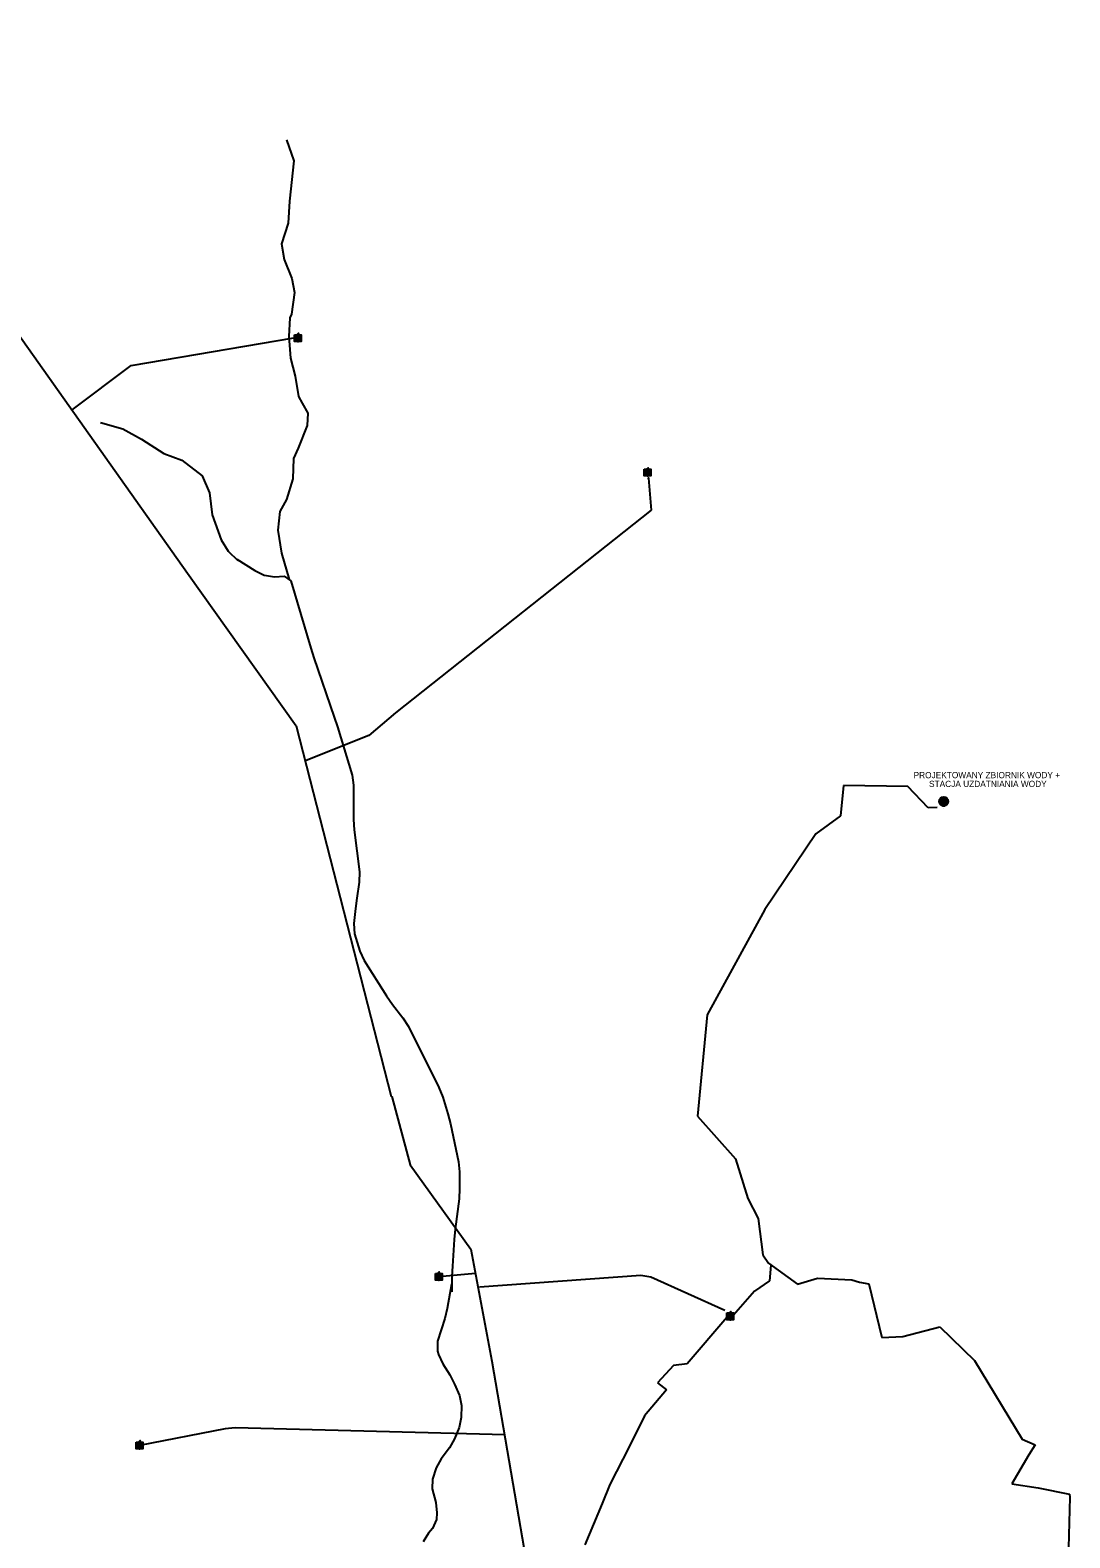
# Model space of a CAD drawing. Extents: x -562329 to -547582, y 191173 to 206137.
# Drawn here: x -557916 to -555907, y 202704 to 205618 of the extents above; entities that cross this region are included whole.
import ezdxf

# ---------------------------------------------------------------- set-up
doc = ezdxf.new("R2010")
doc.units = 0
for name, color, linetype in [('nazwy miejscowości', 7, 'Continuous'), ('nazwy miejscowości DUŻE', 7, 'Continuous'), ('opisy', 7, 'Continuous'), ('ramki A3_A', 7, 'Continuous'), ('strefa - cmentarz', 7, 'Continuous'), ('zmiany', 7, 'Continuous')]:
    doc.layers.add(name, color=color, linetype=linetype)

msp = doc.modelspace()

# ---------------------------------------------------------------- linework, layer by layer
at = {"layer": 'nazwy miejscowości'}
for p, q in [((-556720.8, 204754), (-556723.3, 204751.4)), ((-556721.6, 204752.3), (-556716.5, 204690.4)), ((-556719.9, 204728.5), (-556719.9, 204728.5)), ((-556716.5, 204690.4), (-557210.5, 204299)), ((-557210.5, 204299), (-557262.2, 204254.9)), ((-557262.2, 204254.9), (-557383.3, 204206.6)), ((-557055.8, 203215.2), (-557126.8, 203208.9)), ((-557048.2, 203189.8), (-556736.2, 203212)), ((-556736.2, 203212), (-556717.1, 203208.6)), ((-556717.1, 203208.6), (-556574, 203144.2))]:
    msp.add_line(p, q, dxfattribs=at)
for points in [[(-558670.2, 205618.4), (-558633.4, 205559), (-558588.2, 205493.7), (-557970.8, 205075.8), (-557612.3, 204568.8)], [(-557835.5, 204884.6), (-557721.5, 204970.1), (-557406.9, 205023.5)], [(-557612.3, 204568.8), (-557402.2, 204273.9), (-557219, 203557.1)], [(-557217.5, 203557.5), (-557181.9, 203425), (-557065.2, 203262.5), (-557024.6, 203046), (-556950.7, 202618.3), (-556938.9, 202550.3)]]:
    msp.add_lwpolyline(points, dxfattribs=at)
at = {"layer": 'nazwy miejscowości DUŻE'}
for p, q in [((-557539.8, 202915.3), (-557704.9, 202883)), ((-557520, 202917), (-557539.8, 202915.3)), ((-556998.8, 202903.3), (-557520, 202917))]:
    msp.add_line(p, q, dxfattribs=at)
at = {"layer": 'opisy'}
for p, q in [((-556344.9, 204158.5), (-556350.4, 204099.9)), ((-556344.9, 204158.5), (-556350.4, 204099.9)), ((-556220.4, 204156.7), (-556344.9, 204158.5)), ((-556220.4, 204156.7), (-556344.9, 204158.5)), ((-556180.9, 204115.2), (-556220.4, 204156.7)), ((-556180.9, 204115.2), (-556220.4, 204156.7)), ((-556350.4, 204099.9), (-556398, 204065.1)), ((-556350.4, 204099.9), (-556398, 204065.1)), ((-556163.5, 204115.9), (-556180.9, 204115.2)), ((-556163.5, 204115.9), (-556180.9, 204115.2)), ((-556398, 204065.1), (-556496.9, 203918.7)), ((-556398, 204065.1), (-556496.9, 203918.7)), ((-556496.9, 203918.7), (-556608.5, 203715.5)), ((-556496.9, 203918.7), (-556608.5, 203715.5)), ((-556608.5, 203715.5), (-556626.9, 203519.6)), ((-556608.5, 203715.5), (-556626.9, 203519.6)), ((-556626.9, 203519.6), (-556553.6, 203437.2)), ((-556626.9, 203519.6), (-556553.6, 203437.2)), ((-556553.6, 203437.2), (-556529.8, 203360.3)), ((-556553.6, 203437.2), (-556529.8, 203360.3)), ((-556529.8, 203360.3), (-556509.7, 203321.8)), ((-556529.8, 203360.3), (-556509.7, 203321.8)), ((-556509.7, 203321.8), (-556500.9, 203251.4)), ((-556509.7, 203321.8), (-556500.9, 203251.4)), ((-556500.9, 203251.4), (-556489.6, 203235)), ((-556500.9, 203251.4), (-556489.6, 203235)), ((-556489.6, 203235), (-556433.7, 203194.5)), ((-556489.6, 203235), (-556433.7, 203194.5)), ((-556485.1, 203231.7), (-556487.7, 203201.1)), ((-556487.7, 203201.1), (-556516.7, 203180.9)), ((-556433.7, 203194.5), (-556394.9, 203206.5)), ((-556433.7, 203194.5), (-556394.9, 203206.5)), ((-556394.9, 203206.5), (-556328.6, 203203.1)), ((-556394.9, 203206.5), (-556328.6, 203203.1)), ((-556328.6, 203203.1), (-556314.2, 203198.6)), ((-556328.6, 203203.1), (-556314.2, 203198.6)), ((-556314.2, 203198.6), (-556295.6, 203195.4)), ((-556314.2, 203198.6), (-556295.6, 203195.4)), ((-556295.6, 203195.4), (-556270.6, 203091.3)), ((-556295.6, 203195.4), (-556270.6, 203091.3)), ((-556516.7, 203180.9), (-556557.1, 203134.9)), ((-556570, 203130), (-556646.7, 203040.5)), ((-556557.1, 203134.9), (-556570, 203130)), ((-556230.3, 203093.7), (-556158.4, 203112.3)), ((-556230.3, 203093.7), (-556158.4, 203112.3)), ((-556158.4, 203112.3), (-556091.4, 203046.9)), ((-556158.4, 203112.3), (-556091.4, 203046.9)), ((-556270.6, 203091.3), (-556230.3, 203093.7)), ((-556270.6, 203091.3), (-556230.3, 203093.7)), ((-556673.3, 203037.2), (-556704, 203004.2)), ((-556646.7, 203040.5), (-556673.3, 203037.2)), ((-556091.4, 203046.9), (-555999.4, 202894.8)), ((-556091.4, 203046.9), (-555999.4, 202894.8)), ((-556687, 202990.4), (-556729, 202940.4)), ((-556704, 203004.2), (-556687, 202990.4)), ((-556729, 202940.4), (-556758, 202881.5)), ((-556758, 202881.5), (-556796, 202807.2)), ((-555999.4, 202894.8), (-555974.4, 202883.9)), ((-555974.4, 202883.9), (-555986.5, 202864.5)), ((-555986.5, 202864.5), (-556019.6, 202808.9)), ((-556796, 202807.2), (-556811.3, 202770.9)), ((-556019.6, 202808.9), (-555968.8, 202800.8)), ((-555968.8, 202800.8), (-555908.3, 202788.7)), ((-555908.3, 202788.7), (-555907.5, 202783)), ((-556811.3, 202770.9), (-556844.4, 202690.6)), ((-555907.5, 202783), (-555910.7, 202660.4))]:
    msp.add_line(p, q, dxfattribs=at)
at = {"layer": 'ramki A3_A'}
for p, q in [((-557399.6, 205029.7), (-557402.1, 205021.4)), ((-557401.1, 205029.7), (-557399.6, 205029.7)), ((-557400, 205023.6), (-557398.1, 205029.7)), ((-557398.1, 205029.7), (-557396.6, 205029.7)), ((-557403.6, 205018.4), (-557403.6, 205027.9)), ((-557403.6, 205027.9), (-557400.1, 205027.9)), ((-557399.1, 205018.4), (-557403.6, 205018.4)), ((-557402.1, 205021.4), (-557397.8, 205022.8)), ((-557395.6, 205025), (-557400, 205023.6)), ((-557397.8, 205022.8), (-557399.6, 205016.7)), ((-557399.6, 205016.7), (-557398.1, 205016.7)), ((-557399.6, 205016.7), (-557398.1, 205016.7)), ((-557398.6, 205027.9), (-557394.1, 205027.9)), ((-557398.1, 205016.7), (-557395.6, 205025)), ((-557394.1, 205018.4), (-557397.6, 205018.4)), ((-557394.1, 205027.9), (-557394.1, 205018.4)), ((-556728.1, 204758.4), (-556728.1, 204767.9)), ((-556728.1, 204767.9), (-556724.6, 204767.9)), ((-556724.1, 204769.6), (-556726.6, 204761.3)), ((-556725.6, 204769.6), (-556724.1, 204769.6)), ((-556724.4, 204763.6), (-556722.6, 204769.6)), ((-556723.1, 204767.9), (-556718.6, 204767.9)), ((-556722.6, 204769.6), (-556721.1, 204769.6)), ((-556718.6, 204767.9), (-556718.6, 204758.4)), ((-556723.6, 204758.4), (-556728.1, 204758.4)), ((-556726.6, 204761.3), (-556722.3, 204762.8)), ((-556720.1, 204765), (-556724.4, 204763.6)), ((-556722.3, 204762.8), (-556724.1, 204756.7)), ((-556724.1, 204756.7), (-556722.6, 204756.7)), ((-556724.1, 204756.7), (-556722.6, 204756.7)), ((-556722.6, 204756.7), (-556720.1, 204765)), ((-556718.6, 204758.4), (-556722.1, 204758.4)), ((-557131.6, 203204.1), (-557131.6, 203213.6)), ((-557131.6, 203213.6), (-557128.1, 203213.6)), ((-557127, 203204.1), (-557131.6, 203204.1)), ((-557127.6, 203215.3), (-557130.1, 203207)), ((-557130.1, 203207), (-557125.7, 203208.5)), ((-557129.1, 203215.3), (-557127.6, 203215.3)), ((-557127.9, 203209.2), (-557126.1, 203215.3)), ((-557123.6, 203210.7), (-557127.9, 203209.2)), ((-557125.7, 203208.5), (-557127.6, 203202.4)), ((-557127.6, 203202.4), (-557126.1, 203202.4)), ((-557127.6, 203202.4), (-557126.1, 203202.4)), ((-557126.6, 203213.6), (-557122.1, 203213.6)), ((-557126.1, 203215.3), (-557124.6, 203215.3)), ((-557126.1, 203202.4), (-557123.6, 203210.7)), ((-557122.1, 203204.1), (-557125.6, 203204.1)), ((-557122.1, 203213.6), (-557122.1, 203204.1)), ((-556568.3, 203127.7), (-556568.3, 203137.2)), ((-556568.3, 203137.2), (-556564.8, 203137.2)), ((-556564.3, 203139), (-556566.8, 203130.6)), ((-556565.8, 203139), (-556564.3, 203139)), ((-556564.6, 203132.9), (-556562.8, 203139)), ((-556563.3, 203137.2), (-556558.8, 203137.2)), ((-556562.8, 203139), (-556561.3, 203139)), ((-556558.8, 203137.2), (-556558.8, 203127.7)), ((-556563.8, 203127.7), (-556568.3, 203127.7)), ((-556566.8, 203130.6), (-556562.5, 203132.1)), ((-556560.3, 203134.3), (-556564.6, 203132.9)), ((-556562.5, 203132.1), (-556564.3, 203126)), ((-556564.3, 203126), (-556562.8, 203126)), ((-556564.3, 203126), (-556562.8, 203126)), ((-556562.8, 203126), (-556560.3, 203134.3)), ((-556558.8, 203127.7), (-556562.3, 203127.7)), ((-557709.7, 202878.3), (-557709.7, 202887.8)), ((-557709.7, 202887.8), (-557706.2, 202887.8)), ((-557705.2, 202878.3), (-557709.7, 202878.3)), ((-557705.7, 202889.5), (-557708.2, 202881.2)), ((-557708.2, 202881.2), (-557703.9, 202882.6)), ((-557707.2, 202889.5), (-557705.7, 202889.5)), ((-557706, 202883.4), (-557704.2, 202889.5)), ((-557701.7, 202884.9), (-557706, 202883.4)), ((-557703.9, 202882.6), (-557705.7, 202876.5)), ((-557705.7, 202876.5), (-557704.2, 202876.5)), ((-557705.7, 202876.5), (-557704.2, 202876.5)), ((-557704.7, 202887.8), (-557700.2, 202887.8)), ((-557704.2, 202889.5), (-557702.7, 202889.5)), ((-557704.2, 202876.5), (-557701.7, 202884.9)), ((-557700.2, 202878.3), (-557703.7, 202878.3)), ((-557700.2, 202887.8), (-557700.2, 202878.3))]:
    msp.add_line(p, q, dxfattribs=at)
for points in [[(-557405.4, 205029.7), (-557392.4, 205029.7), (-557392.4, 205016.7), (-557405.4, 205016.7)], [(-556729.8, 204769.6), (-556716.9, 204769.6), (-556716.9, 204756.7), (-556729.8, 204756.7)], [(-557133.3, 203215.3), (-557120.3, 203215.3), (-557120.3, 203202.4), (-557133.3, 203202.4)], [(-556570, 203139), (-556557.1, 203139), (-556557.1, 203126), (-556570, 203126)], [(-557711.4, 202889.5), (-557698.5, 202889.5), (-557698.5, 202876.5), (-557711.4, 202876.5)]]:
    msp.add_lwpolyline(points, close=True, dxfattribs=at)
for points in [[(-557396.6, 205029.7), (-557398, 205032.5), (-557401.1, 205029.7)], [(-556721.1, 204769.6), (-556722.5, 204772.5), (-556725.6, 204769.6)], [(-557124.6, 203215.3), (-557126, 203218.2), (-557129.1, 203215.3)], [(-556561.3, 203139), (-556562.7, 203141.8), (-556565.8, 203139)], [(-557702.7, 202889.5), (-557704.1, 202892.4), (-557707.2, 202889.5)]]:
    msp.add_lwpolyline(points, dxfattribs=at)
at = {"layer": 'strefa - cmentarz'}
for p, q in [((-556157.2, 204127.8), (-556159.8, 204127.8)), ((-556147.7, 204127.8), (-556154.6, 204127.8)), ((-556142.5, 204127.8), (-556145.1, 204127.8)), ((-556151.2, 204114.3), (-556151.2, 204114.3))]:
    msp.add_line(p, q, dxfattribs=at)
for radius in [8.66, 6.06, 3.46]:
    msp.add_circle((-556151.2, 204127.8), radius, dxfattribs=at)
for radius, start, end in [(8.66, 180, 240), (6.06, 180, 0), (8.66, 240, 0), (3.46, 180, 240), (3.46, 240, 0)]:
    msp.add_arc((-556151.2, 204127.8), radius, start, end, dxfattribs=at)
at = {"layer": 'zmiany'}
for p, q in [((-557517, 204595.8), (-557482.3, 204574)), ((-557482.3, 204574), (-557464.4, 204565.1)), ((-557464.4, 204565.1), (-557463.4, 204564.7)), ((-557463.4, 204564.7), (-557444.1, 204561.9)), ((-557444.1, 204561.9), (-557425.8, 204563.1)), ((-557425.8, 204563.1), (-557413, 204554.1)), ((-557413, 204554.1), (-557374.3, 204424)), ((-557374.3, 204424), (-557368.2, 204405)), ((-557368.2, 204405), (-557329, 204290.7)), ((-557329, 204290.7), (-557322.8, 204271.7)), ((-557322.8, 204271.7), (-557294.2, 204178.6)), ((-557294.2, 204178.6), (-557291.3, 204159)), ((-557291.3, 204159), (-557291.3, 204092.7)), ((-557291.3, 204092.7), (-557290, 204072.7)), ((-557290, 204072.7), (-557280.1, 203991.5)), ((-557280.1, 203991.5), (-557280.4, 203971.6)), ((-557280.4, 203971.6), (-557284.9, 203940.9)), ((-557284.9, 203940.9), (-557287.6, 203921)), ((-557287.6, 203921), (-557291.2, 203891.5)), ((-557291.2, 203891.5), (-557289.6, 203872)), ((-557289.6, 203872), (-557279.3, 203838.2)), ((-557279.3, 203838.2), (-557271.1, 203820.2)), ((-557271.1, 203820.2), (-557227.6, 203751.9)), ((-557227.6, 203751.9), (-557216.1, 203735.5)), ((-557216.1, 203735.5), (-557196.2, 203709.5)), ((-557196.2, 203709.5), (-557185.6, 203692.6)), ((-557185.6, 203692.6), (-557126.7, 203574.8)), ((-557126.7, 203574.8), (-557119.3, 203556.3)), ((-557119.3, 203556.3), (-557109.2, 203523.6)), ((-557109.2, 203523.6), (-557104.2, 203504.3)), ((-557104.2, 203504.3), (-557088.6, 203431.3)), ((-557088.6, 203431.3), (-557086.5, 203411.6)), ((-557086.5, 203411.6), (-557086.5, 203379.8)), ((-557086.5, 203379.8), (-557087.7, 203359.8)), ((-557087.7, 203359.8), (-557095.1, 203300.7)), ((-557095.1, 203300.7), (-557097.1, 203280.8)), ((-557097.1, 203280.8), (-557100.6, 203229.3)), ((-557100.6, 203229.3), (-557101.3, 203209.3)), ((-557102.5, 203194.6), (-557110.7, 203147.7)), ((-557101.3, 203209.3), (-557101.3, 203179.8)), ((-557110.7, 203147.7), (-557115.4, 203128.3)), ((-557115.4, 203128.3), (-557129.2, 203084.5)), ((-557129.2, 203084.5), (-557129.4, 203065.4)), ((-557129.4, 203065.4), (-557127.5, 203058.7)), ((-557127.5, 203058.7), (-557119.3, 203040.7)), ((-557119.3, 203040.7), (-557105.5, 203019.2)), ((-557105.5, 203019.2), (-557096.2, 203001.6)), ((-557096.2, 203001.6), (-557086.7, 202979.3)), ((-557086.7, 202979.3), (-557083.1, 202960.1)), ((-557083.8, 202937), (-557087.7, 202917.7)), ((-557083.1, 202960.1), (-557083.8, 202937)), ((-557087.7, 202917.7), (-557096.4, 202895.6)), ((-557106.2, 202878.3), (-557122.4, 202857.2)), ((-557096.4, 202895.6), (-557106.2, 202878.3)), ((-557122.4, 202857.2), (-557131.6, 202839.8)), ((-557138.8, 202818), (-557139.4, 202798.9)), ((-557131.6, 202839.8), (-557138.8, 202818)), ((-557139.4, 202798.9), (-557132.3, 202772.6)), ((-557132.3, 202772.6), (-557130.4, 202752.9)), ((-557131.4, 202739.6), (-557138.8, 202722.2)), ((-557130.4, 202752.9), (-557131.4, 202739.6)), ((-557146.4, 202713.6), (-557156.7, 202696.8)), ((-557138.8, 202722.2), (-557146.4, 202713.6))]:
    msp.add_line(p, q, dxfattribs=at)
for points in [[(-557421.1, 205406.3), (-557406.8, 205365.7), (-557415.1, 205287.6), (-557418.1, 205245.5), (-557430.9, 205205.7), (-557425.6, 205174.9), (-557410.6, 205138.1), (-557405.3, 205111.1), (-557411.4, 205069.7), (-557414.4, 205062.2), (-557416.6, 205026.2), (-557413.6, 204984.1), (-557404.6, 204949.5), (-557397.8, 204910.5), (-557391.1, 204897.7), (-557379.8, 204878.2), (-557381.3, 204854.1), (-557398.6, 204810.5), (-557407.6, 204790.2), (-557409.1, 204751.2), (-557421.1, 204711.4), (-557433.9, 204688.1), (-557437.6, 204652), (-557430.9, 204607.7), (-557415.9, 204556.6)], [(-557780.2, 204860.1), (-557737.4, 204848.1), (-557701.4, 204827.8), (-557657.8, 204800), (-557623.2, 204787.2), (-557584.2, 204757.2), (-557569.9, 204724.1), (-557564.6, 204681.3), (-557547.3, 204633.2), (-557533.8, 204611.4), (-557515, 204593.4)]]:
    msp.add_lwpolyline(points, dxfattribs=at)

# ---------------------------------------------------------------- texts
at = {"layer": 'opisy'}
for s, p in [('PROJEKTOWANY ZBIORNIK WODY + ', (-556209.4, 204172.6)), ('STACJA UZDATNIANIA WODY', (-556179.5, 204155.6))]:
    msp.add_text(s, height=12, dxfattribs=at).set_placement(p)

doc.saveas('drawing.dxf')
